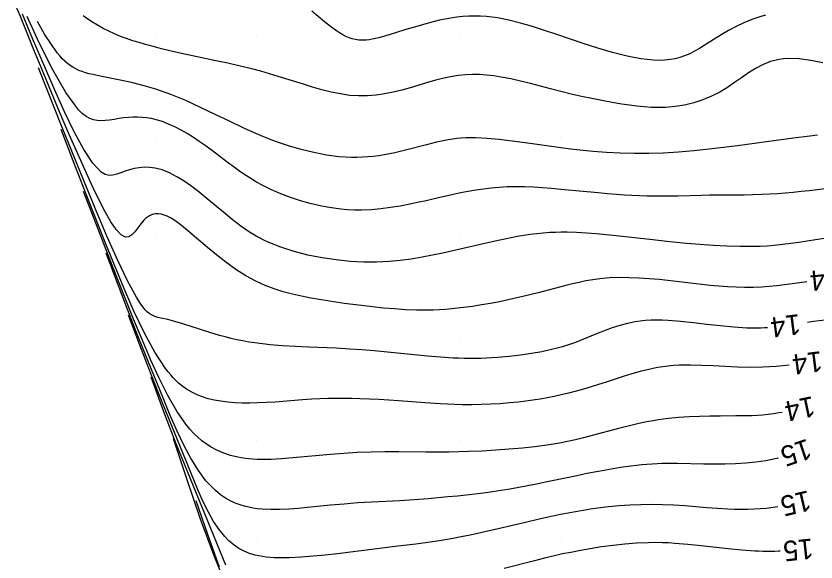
# Model space of a CAD drawing. Extents: x 2602990 to 2605851, y 618069 to 619180.
# Drawn here: x 2603136.2 to 2603215.3, y 618118 to 618172 of the extents above; entities that cross this region are included whole.
import ezdxf

# ---------------------------------------------------------------- set-up
doc = ezdxf.new("R2010")
doc.units = 0
for name, color, linetype in [('DTM Contours Major', 7, 'Continuous'), ('DTM Contours Major Text', 7, 'Continuous'), ('DTM Contours Minor', 7, 'Continuous'), ('DTM Contours Minor Text', 7, 'Continuous'), ('Exist DTM QL2 LIDAR Elevation Point', 7, 'Continuous')]:
    doc.layers.add(name, color=color, linetype=linetype)

msp = doc.modelspace()

# ---------------------------------------------------------------- linework, layer by layer
at = {"layer": 'DTM Contours Major'}
for points in [[(2603210.47, 618141.157), (2603210.172, 618141.14), (2603209.828, 618141.126), (2603209.483, 618141.118), (2603209.137, 618141.115), (2603208.788, 618141.118), (2603208.436, 618141.127), (2603207.132, 618141.204), (2603205.803, 618141.331), (2603204.471, 618141.486), (2603203.155, 618141.646), (2603201.878, 618141.786), (2603200.658, 618141.883), (2603200.075, 618141.909), (2603199.509, 618141.916), (2603198.959, 618141.905), (2603198.424, 618141.873), (2603197.901, 618141.821), (2603197.389, 618141.746), (2603196.617, 618141.586), (2603195.865, 618141.381), (2603195.133, 618141.142), (2603194.421, 618140.88), (2603193.728, 618140.605), (2603192.276, 618140.012), (2603191.89, 618139.861), (2603191.503, 618139.714), (2603191.111, 618139.572), (2603190.712, 618139.437), (2603190.206, 618139.279), (2603189.68, 618139.13), (2603189.129, 618138.99), (2603188.16, 618138.78), (2603187.127, 618138.594), (2603186.045, 618138.437), (2603184.929, 618138.308), (2603183.797, 618138.211), (2603182.663, 618138.147), (2603182.12, 618138.128), (2603181.578, 618138.118), (2603181.036, 618138.115), (2603180.491, 618138.121), (2603179.941, 618138.136), (2603179.384, 618138.158), (2603178.131, 618138.236), (2603176.846, 618138.343), (2603175.539, 618138.471), (2603172.902, 618138.745), (2603171.593, 618138.87), (2603170.38, 618138.97), (2603169.163, 618139.052), (2603167.819, 618139.125), (2603165.119, 618139.245), (2603163.801, 618139.308), (2603162.527, 618139.383), (2603161.317, 618139.478), (2603160.544, 618139.558), (2603159.799, 618139.653), (2603159.197, 618139.746), (2603158.606, 618139.852), (2603158.024, 618139.971), (2603157.448, 618140.103), (2603156.875, 618140.247), (2603156.302, 618140.404), (2603155.354, 618140.686), (2603154.419, 618140.984), (2603152.66, 618141.554), (2603151.876, 618141.79), (2603151.181, 618141.969), (2603150.493, 618142.108), (2603150.188, 618142.177), (2603149.902, 618142.265), (2603149.628, 618142.388), (2603149.359, 618142.561), (2603149.159, 618142.73), (2603148.956, 618142.937), (2603148.748, 618143.185), (2603148.534, 618143.474), (2603148.312, 618143.807), (2603148.079, 618144.186), (2603147.212, 618145.792), (2603146.241, 618147.819), (2603145.204, 618150.147), (2603144.137, 618152.655), (2603143.077, 618155.223), (2603142.059, 618157.732), (2603140.756, 618160.976), (2603138.407, 618166.881)], [(2603216.138, 618141.923), (2603215.029, 618141.76), (2603214.435, 618141.666)]]:
    msp.add_lwpolyline(points, dxfattribs=at)
at = {"layer": 'DTM Contours Minor'}
for points in [[(2603214.371, 618145.696), (2603212.917, 618145.499), (2603212.16, 618145.402), (2603211.404, 618145.314), (2603210.647, 618145.242), (2603209.889, 618145.188), (2603209.053, 618145.155), (2603208.213, 618145.149), (2603207.368, 618145.166), (2603206.519, 618145.206), (2603205.666, 618145.264), (2603204.809, 618145.34), (2603203.981, 618145.427), (2603202.313, 618145.625), (2603200.627, 618145.826), (2603199.776, 618145.916), (2603198.78, 618146.005), (2603197.784, 618146.071), (2603196.792, 618146.11), (2603195.812, 618146.114), (2603194.849, 618146.079), (2603193.911, 618145.999), (2603193.211, 618145.906), (2603192.527, 618145.787), (2603191.854, 618145.649), (2603191.189, 618145.494), (2603190.531, 618145.33), (2603187.814, 618144.62), (2603187.119, 618144.443), (2603186.417, 618144.271), (2603185.707, 618144.104), (2603184.842, 618143.913), (2603183.967, 618143.733), (2603183.084, 618143.565), (2603182.198, 618143.412), (2603181.31, 618143.275), (2603180.425, 618143.155), (2603179.831, 618143.085), (2603179.237, 618143.025), (2603178.641, 618142.975), (2603178.04, 618142.937), (2603177.432, 618142.91), (2603176.813, 618142.897), (2603175.768, 618142.904), (2603174.697, 618142.945), (2603173.609, 618143.015), (2603172.512, 618143.108), (2603171.414, 618143.22), (2603170.324, 618143.345), (2603169.477, 618143.452), (2603168.638, 618143.565), (2603167.806, 618143.685), (2603166.977, 618143.814), (2603166.152, 618143.952), (2603165.327, 618144.1), (2603164.418, 618144.278), (2603163.511, 618144.479), (2603162.607, 618144.714), (2603161.71, 618144.992), (2603160.822, 618145.323), (2603159.946, 618145.718), (2603158.91, 618146.285), (2603157.903, 618146.932), (2603156.929, 618147.634), (2603155.996, 618148.364), (2603155.111, 618149.097), (2603153.37, 618150.586), (2603152.945, 618150.94), (2603152.537, 618151.266), (2603152.147, 618151.559), (2603151.773, 618151.817), (2603151.444, 618152.018), (2603151.127, 618152.183), (2603150.822, 618152.309), (2603150.529, 618152.395), (2603150.248, 618152.438), (2603149.978, 618152.435), (2603149.767, 618152.397), (2603149.563, 618152.33), (2603149.367, 618152.233), (2603149.178, 618152.111), (2603148.997, 618151.964), (2603148.824, 618151.795), (2603148.513, 618151.425), (2603148.22, 618151.027), (2603147.935, 618150.651), (2603147.647, 618150.343), (2603147.345, 618150.152), (2603147.022, 618150.124), (2603146.583, 618150.361), (2603146.099, 618150.88), (2603145.573, 618151.645), (2603145.009, 618152.622), (2603144.412, 618153.775), (2603143.784, 618155.069), (2603142.978, 618156.808), (2603142.147, 618158.66), (2603141.31, 618160.58), (2603140.482, 618162.518), (2603139.679, 618164.429), (2603138.918, 618166.264), (2603137.943, 618168.642), (2603136.61, 618171.936), (2603136.181, 618173.001)], [(2603210.276, 618172.072), (2603209.73, 618171.924), (2603208.928, 618171.652), (2603208.14, 618171.329), (2603207.371, 618170.964), (2603206.623, 618170.567), (2603205.9, 618170.149), (2603205.204, 618169.719), (2603204.228, 618169.092), (2603203.75, 618168.795), (2603203.271, 618168.518), (2603202.784, 618168.268), (2603202.283, 618168.053), (2603201.821, 618167.895), (2603201.342, 618167.771), (2603200.842, 618167.681), (2603200.318, 618167.625), (2603199.769, 618167.605), (2603199.191, 618167.621), (2603197.937, 618167.762), (2603196.585, 618168.025), (2603195.166, 618168.386), (2603193.707, 618168.816), (2603192.238, 618169.289), (2603189.642, 618170.169), (2603188.424, 618170.577), (2603187.231, 618170.958), (2603186.061, 618171.297), (2603184.916, 618171.583), (2603183.793, 618171.802), (2603182.694, 618171.942), (2603182.105, 618171.981), (2603181.521, 618171.993), (2603180.939, 618171.979), (2603180.356, 618171.941), (2603179.77, 618171.878), (2603179.18, 618171.792), (2603178.049, 618171.57), (2603176.912, 618171.29), (2603175.792, 618170.974), (2603174.709, 618170.646), (2603173.685, 618170.327), (2603172.741, 618170.042), (2603172.381, 618169.939), (2603172.037, 618169.848), (2603171.708, 618169.769), (2603171.392, 618169.703), (2603171.089, 618169.653), (2603170.796, 618169.619), (2603170.61, 618169.607), (2603170.428, 618169.602), (2603170.249, 618169.606), (2603170.072, 618169.618), (2603169.898, 618169.639), (2603169.724, 618169.668), (2603169.415, 618169.744), (2603169.107, 618169.848), (2603168.798, 618169.98), (2603168.487, 618170.14), (2603168.172, 618170.325), (2603167.851, 618170.536), (2603167.28, 618170.957), (2603166.687, 618171.435), (2603165.437, 618172.49)], [(2603216.75, 618150.1), (2603215.203, 618149.854), (2603213.584, 618149.597), (2603212.773, 618149.481), (2603211.957, 618149.378), (2603211.129, 618149.293), (2603210.45, 618149.24), (2603209.755, 618149.202), (2603209.039, 618149.18), (2603207.773, 618149.179), (2603206.457, 618149.217), (2603205.117, 618149.288), (2603203.778, 618149.383), (2603202.469, 618149.495), (2603200.807, 618149.658), (2603198.825, 618149.874), (2603195.524, 618150.243), (2603194.536, 618150.345), (2603193.547, 618150.436), (2603192.565, 618150.512), (2603191.602, 618150.567), (2603190.669, 618150.597), (2603190.085, 618150.601), (2603189.514, 618150.591), (2603188.953, 618150.568), (2603188.305, 618150.522), (2603187.664, 618150.458), (2603187.027, 618150.378), (2603186.395, 618150.284), (2603185.764, 618150.177), (2603185.135, 618150.06), (2603184.491, 618149.932), (2603183.846, 618149.796), (2603182.544, 618149.505), (2603179.358, 618148.763), (2603178.385, 618148.545), (2603177.37, 618148.332), (2603176.324, 618148.133), (2603175.254, 618147.956), (2603174.169, 618147.811), (2603173.076, 618147.707), (2603172.445, 618147.669), (2603171.811, 618147.647), (2603171.173, 618147.642), (2603170.527, 618147.654), (2603169.872, 618147.682), (2603169.205, 618147.726), (2603167.841, 618147.865), (2603166.446, 618148.071), (2603165.047, 618148.347), (2603163.673, 618148.695), (2603162.35, 618149.119), (2603161.105, 618149.619), (2603160.669, 618149.824), (2603160.245, 618150.042), (2603159.914, 618150.225), (2603159.429, 618150.515), (2603159.27, 618150.616), (2603158.396, 618151.217), (2603157.547, 618151.865), (2603156.718, 618152.543), (2603155.096, 618153.914), (2603154.291, 618154.57), (2603153.552, 618155.134), (2603152.813, 618155.648), (2603152.08, 618156.099), (2603151.356, 618156.476), (2603150.645, 618156.764), (2603149.951, 618156.952), (2603149.4, 618157.025), (2603148.866, 618157.033), (2603148.353, 618156.987), (2603147.862, 618156.898), (2603147.398, 618156.777), (2603146.962, 618156.634), (2603146.543, 618156.478), (2603146.148, 618156.34), (2603145.768, 618156.248), (2603145.391, 618156.234), (2603145.01, 618156.324), (2603144.613, 618156.55), (2603143.781, 618157.424), (2603142.88, 618158.793), (2603141.935, 618160.535), (2603140.971, 618162.531), (2603140.013, 618164.661), (2603139.086, 618166.802), (2603137.827, 618169.76), (2603136.81, 618172.183)], [(2603217.226, 618155.04), (2603214.578, 618154.71), (2603213.793, 618154.621), (2603213.011, 618154.541), (2603212.23, 618154.471), (2603211.45, 618154.411), (2603210.668, 618154.363), (2603209.886, 618154.327), (2603209.027, 618154.302), (2603208.167, 618154.289), (2603205.591, 618154.275), (2603204.74, 618154.265), (2603203.951, 618154.248), (2603201.607, 618154.182), (2603200.83, 618154.166), (2603200.054, 618154.158), (2603199.314, 618154.162), (2603198.572, 618154.176), (2603197.827, 618154.201), (2603197.077, 618154.236), (2603196.321, 618154.281), (2603195.556, 618154.334), (2603194.653, 618154.407), (2603193.74, 618154.489), (2603190.032, 618154.848), (2603189.132, 618154.928), (2603188.236, 618154.998), (2603187.346, 618155.053), (2603186.463, 618155.089), (2603185.589, 618155.101), (2603184.726, 618155.085), (2603183.938, 618155.042), (2603183.159, 618154.973), (2603182.388, 618154.881), (2603181.624, 618154.768), (2603180.866, 618154.637), (2603180.112, 618154.49), (2603179.44, 618154.348), (2603178.095, 618154.041), (2603176.732, 618153.724), (2603176.038, 618153.568), (2603175.107, 618153.371), (2603174.16, 618153.192), (2603173.204, 618153.037), (2603172.244, 618152.914), (2603171.284, 618152.831), (2603170.331, 618152.795), (2603169.646, 618152.802), (2603168.965, 618152.837), (2603168.287, 618152.898), (2603167.609, 618152.984), (2603166.929, 618153.094), (2603166.247, 618153.228), (2603165.269, 618153.455), (2603164.291, 618153.725), (2603163.322, 618154.037), (2603162.372, 618154.391), (2603161.451, 618154.786), (2603160.568, 618155.22), (2603159.965, 618155.554), (2603159.384, 618155.906), (2603158.82, 618156.272), (2603158.271, 618156.65), (2603157.733, 618157.037), (2603157.202, 618157.431), (2603155.464, 618158.748), (2603154.885, 618159.175), (2603154.304, 618159.588), (2603153.718, 618159.982), (2603153.111, 618160.363), (2603152.499, 618160.714), (2603151.884, 618161.032), (2603151.269, 618161.31), (2603150.656, 618161.545), (2603150.047, 618161.732), (2603149.574, 618161.842), (2603149.105, 618161.922), (2603148.642, 618161.972), (2603148.184, 618161.994), (2603147.734, 618161.991), (2603147.29, 618161.965), (2603146.808, 618161.91), (2603146.335, 618161.841), (2603145.874, 618161.767), (2603145.424, 618161.701), (2603144.987, 618161.655), (2603144.562, 618161.639), (2603144.203, 618161.661), (2603143.848, 618161.727), (2603143.493, 618161.853), (2603143.132, 618162.049), (2603142.759, 618162.33), (2603142.37, 618162.708), (2603141.111, 618164.417), (2603139.733, 618166.833), (2603138.308, 618169.704), (2603137.279, 618171.962)], [(2603215.943, 618167.362), (2603214.745, 618167.606), (2603213.601, 618167.751), (2603212.526, 618167.777), (2603212.068, 618167.744), (2603211.627, 618167.684), (2603211.199, 618167.596), (2603210.784, 618167.48), (2603210.38, 618167.337), (2603209.984, 618167.168), (2603209.285, 618166.798), (2603208.598, 618166.364), (2603207.913, 618165.892), (2603207.221, 618165.404), (2603206.51, 618164.924), (2603205.771, 618164.476), (2603204.943, 618164.056), (2603204.079, 618163.701), (2603203.186, 618163.411), (2603202.271, 618163.189), (2603201.343, 618163.034), (2603200.409, 618162.949), (2603199.699, 618162.93), (2603198.988, 618162.947), (2603198.273, 618162.996), (2603197.553, 618163.07), (2603196.825, 618163.165), (2603196.087, 618163.276), (2603195.106, 618163.44), (2603194.109, 618163.623), (2603193.1, 618163.823), (2603192.083, 618164.04), (2603191.063, 618164.273), (2603190.043, 618164.522), (2603189.031, 618164.783), (2603187.033, 618165.308), (2603186.054, 618165.552), (2603185.092, 618165.771), (2603184.149, 618165.955), (2603183.421, 618166.069), (2603182.705, 618166.152), (2603181.999, 618166.201), (2603181.3, 618166.214), (2603180.606, 618166.187), (2603179.916, 618166.119), (2603179.128, 618165.99), (2603178.339, 618165.814), (2603177.548, 618165.604), (2603176.754, 618165.373), (2603175.15, 618164.893), (2603174.315, 618164.664), (2603173.474, 618164.459), (2603172.626, 618164.289), (2603171.773, 618164.163), (2603170.915, 618164.092), (2603170.054, 618164.083), (2603169.151, 618164.148), (2603168.246, 618164.281), (2603167.337, 618164.47), (2603166.425, 618164.701), (2603165.509, 618164.964), (2603164.588, 618165.245), (2603162.095, 618166.023), (2603161.246, 618166.277), (2603160.384, 618166.523), (2603159.507, 618166.759), (2603158.326, 618167.048), (2603157.132, 618167.317), (2603155.94, 618167.569), (2603153.632, 618168.046), (2603152.549, 618168.279), (2603151.528, 618168.515), (2603150.561, 618168.755), (2603149.631, 618168.999), (2603148.986, 618169.176), (2603148.352, 618169.36), (2603147.729, 618169.553), (2603147.117, 618169.758), (2603146.516, 618169.98), (2603145.927, 618170.222), (2603145.349, 618170.486), (2603144.783, 618170.774), (2603144.227, 618171.084), (2603143.683, 618171.417), (2603143.148, 618171.772), (2603142.836, 618171.998)], [(2603215.405, 618160.195), (2603214.647, 618160.112), (2603213.047, 618159.918), (2603211.331, 618159.694), (2603207.511, 618159.169), (2603206.112, 618158.984), (2603204.663, 618158.807), (2603203.177, 618158.649), (2603201.671, 618158.521), (2603200.161, 618158.432), (2603198.73, 618158.392), (2603197.316, 618158.393), (2603195.923, 618158.431), (2603194.557, 618158.502), (2603193.225, 618158.602), (2603191.932, 618158.726), (2603190.984, 618158.833), (2603190.051, 618158.95), (2603189.119, 618159.077), (2603186.507, 618159.453), (2603185.216, 618159.63), (2603183.956, 618159.779), (2603182.746, 618159.888), (2603181.602, 618159.941), (2603181.126, 618159.944), (2603180.661, 618159.932), (2603180.205, 618159.905), (2603179.775, 618159.865), (2603179.377, 618159.815), (2603178.904, 618159.74), (2603178.744, 618159.712), (2603177.766, 618159.508), (2603176.757, 618159.263), (2603174.679, 618158.728), (2603173.625, 618158.477), (2603172.572, 618158.265), (2603172.039, 618158.177), (2603171.506, 618158.106), (2603170.972, 618158.052), (2603170.433, 618158.016), (2603169.889, 618157.999), (2603169.338, 618158.002), (2603168.12, 618158.079), (2603166.874, 618158.243), (2603165.616, 618158.484), (2603164.362, 618158.79), (2603163.128, 618159.15), (2603161.931, 618159.555), (2603161.251, 618159.808), (2603160.579, 618160.076), (2603159.907, 618160.36), (2603159.066, 618160.736), (2603158.635, 618160.935), (2603157.293, 618161.577), (2603155.886, 618162.261), (2603154.434, 618162.954), (2603152.956, 618163.624), (2603151.475, 618164.238), (2603150.009, 618164.762), (2603148.851, 618165.104), (2603147.726, 618165.383), (2603146.646, 618165.616), (2603144.659, 618166.007), (2603143.774, 618166.199), (2603143.412, 618166.288), (2603143.066, 618166.385), (2603142.732, 618166.494), (2603142.409, 618166.619), (2603142.096, 618166.764), (2603141.79, 618166.933), (2603141.53, 618167.102), (2603141.272, 618167.296), (2603141.015, 618167.515), (2603140.758, 618167.764), (2603140.499, 618168.045), (2603140.236, 618168.36), (2603138.997, 618170.2), (2603138.318, 618171.455)], [(2603212.628, 618137.453), (2603212.613, 618137.451), (2603211.314, 618137.325), (2603210.011, 618137.248), (2603208.758, 618137.232), (2603207.518, 618137.26), (2603206.3, 618137.315), (2603205.112, 618137.379), (2603203.962, 618137.433), (2603202.859, 618137.46), (2603202.291, 618137.457), (2603201.736, 618137.44), (2603201.192, 618137.408), (2603200.656, 618137.361), (2603200.127, 618137.296), (2603199.6, 618137.214), (2603198.747, 618137.042), (2603197.896, 618136.83), (2603197.047, 618136.588), (2603196.2, 618136.325), (2603194.513, 618135.775), (2603193.771, 618135.537), (2603193.03, 618135.308), (2603192.289, 618135.088), (2603191.548, 618134.88), (2603190.806, 618134.686), (2603190.063, 618134.507), (2603189.376, 618134.358), (2603188.686, 618134.223), (2603187.992, 618134.101), (2603187.291, 618133.992), (2603186.583, 618133.896), (2603185.865, 618133.81), (2603184.954, 618133.719), (2603184.03, 618133.645), (2603183.098, 618133.59), (2603182.163, 618133.553), (2603181.228, 618133.537), (2603180.297, 618133.542), (2603179.562, 618133.562), (2603178.831, 618133.592), (2603178.1, 618133.633), (2603176.635, 618133.733), (2603174.004, 618133.93), (2603173.048, 618133.995), (2603172.09, 618134.054), (2603171.133, 618134.103), (2603170.179, 618134.14), (2603169.38, 618134.159), (2603168.584, 618134.167), (2603167.791, 618134.164), (2603166.999, 618134.149), (2603166.207, 618134.122), (2603165.414, 618134.082), (2603164.509, 618134.022), (2603161.81, 618133.811), (2603160.926, 618133.754), (2603160.056, 618133.714), (2603159.299, 618133.699), (2603158.556, 618133.705), (2603157.829, 618133.737), (2603157.12, 618133.795), (2603156.429, 618133.883), (2603155.759, 618134.004), (2603155.184, 618134.14), (2603154.625, 618134.309), (2603154.081, 618134.519), (2603153.551, 618134.776), (2603153.034, 618135.086), (2603152.53, 618135.455), (2603152.262, 618135.682), (2603151.998, 618135.929), (2603151.735, 618136.197), (2603151.474, 618136.488), (2603151.213, 618136.802), (2603150.953, 618137.14), (2603149.912, 618138.727), (2603148.872, 618140.636), (2603147.841, 618142.787), (2603146.827, 618145.097), (2603145.838, 618147.502), (2603144.884, 618149.868), (2603143.403, 618153.626), (2603141.999, 618157.232), (2603140.633, 618160.76)], [(2603211.907, 618132.776), (2603211.617, 618132.726), (2603211.071, 618132.644), (2603210.53, 618132.576), (2603209.991, 618132.523), (2603209.471, 618132.485), (2603208.947, 618132.459), (2603208.418, 618132.443), (2603207.334, 618132.43), (2603205.793, 618132.425), (2603204.782, 618132.416), (2603203.751, 618132.393), (2603202.715, 618132.351), (2603201.686, 618132.284), (2603200.676, 618132.184), (2603200.177, 618132.12), (2603199.684, 618132.046), (2603199.196, 618131.964), (2603198.711, 618131.873), (2603198.229, 618131.775), (2603197.747, 618131.67), (2603196.818, 618131.451), (2603195.889, 618131.216), (2603193.155, 618130.49), (2603192.278, 618130.266), (2603191.496, 618130.079), (2603190.718, 618129.909), (2603189.925, 618129.754), (2603189.302, 618129.646), (2603188.652, 618129.545), (2603187.482, 618129.389), (2603186.238, 618129.252), (2603184.94, 618129.134), (2603183.607, 618129.036), (2603182.26, 618128.959), (2603180.919, 618128.902), (2603179.945, 618128.874), (2603178.972, 618128.857), (2603177.99, 618128.85), (2603176.693, 618128.853), (2603174.017, 618128.872), (2603172.652, 618128.87), (2603171.279, 618128.849), (2603169.907, 618128.8), (2603168.576, 618128.719), (2603167.263, 618128.615), (2603163.541, 618128.275), (2603162.409, 618128.189), (2603161.906, 618128.16), (2603161.418, 618128.139), (2603160.942, 618128.128), (2603160.477, 618128.127), (2603160.02, 618128.139), (2603159.571, 618128.164), (2603158.83, 618128.239), (2603158.106, 618128.36), (2603157.4, 618128.532), (2603156.714, 618128.758), (2603156.048, 618129.042), (2603155.404, 618129.39), (2603154.979, 618129.665), (2603154.563, 618129.974), (2603154.156, 618130.32), (2603153.756, 618130.706), (2603153.362, 618131.135), (2603152.973, 618131.61), (2603152.073, 618132.912), (2603151.193, 618134.442), (2603150.328, 618136.159), (2603149.478, 618138.021), (2603148.638, 618139.987), (2603147.806, 618142.014), (2603146.973, 618144.087), (2603146.144, 618146.177), (2603145.32, 618148.281), (2603143.677, 618152.516), (2603142.858, 618154.64)], [(2603211.576, 618128.263), (2603211.234, 618128.18), (2603210.772, 618128.08), (2603210.301, 618127.992), (2603209.82, 618127.915), (2603209.328, 618127.849), (2603208.332, 618127.751), (2603207.304, 618127.69), (2603206.26, 618127.659), (2603205.214, 618127.651), (2603204.185, 618127.66), (2603201.587, 618127.717), (2603201.072, 618127.723), (2603200.562, 618127.724), (2603200.054, 618127.717), (2603199.557, 618127.701), (2603199.057, 618127.676), (2603198.551, 618127.642), (2603198.037, 618127.597), (2603197.511, 618127.542), (2603196.972, 618127.476), (2603195.94, 618127.328), (2603194.863, 618127.148), (2603193.754, 618126.945), (2603192.624, 618126.723), (2603191.485, 618126.489), (2603188.539, 618125.869), (2603187.646, 618125.685), (2603186.759, 618125.509), (2603185.878, 618125.343), (2603185.001, 618125.189), (2603184.136, 618125.05), (2603183.273, 618124.923), (2603182.411, 618124.808), (2603181.549, 618124.702), (2603180.686, 618124.604), (2603179.821, 618124.512), (2603178.86, 618124.416), (2603177.9, 618124.327), (2603176.943, 618124.246), (2603175.995, 618124.172), (2603175.059, 618124.106), (2603174.139, 618124.05), (2603171.335, 618123.909), (2603170.649, 618123.871), (2603169.965, 618123.826), (2603169.299, 618123.776), (2603168.631, 618123.719), (2603167.284, 618123.59), (2603164.996, 618123.36), (2603164.071, 618123.277), (2603163.152, 618123.212), (2603162.246, 618123.173), (2603161.364, 618123.169), (2603160.516, 618123.209), (2603160.061, 618123.253), (2603159.617, 618123.316), (2603159.186, 618123.397), (2603158.765, 618123.5), (2603158.354, 618123.624), (2603157.951, 618123.772), (2603157.42, 618124.013), (2603156.902, 618124.302), (2603156.397, 618124.645), (2603155.906, 618125.044), (2603155.427, 618125.505), (2603154.96, 618126.029), (2603154.224, 618127.024), (2603153.511, 618128.183), (2603152.814, 618129.49), (2603152.124, 618130.926), (2603151.434, 618132.477), (2603150.749, 618134.134), (2603148.909, 618138.644), (2603147.966, 618141.031), (2603147.012, 618143.491), (2603145.084, 618148.52)], [(2603211.499, 618123.434), (2603211.261, 618123.396), (2603210.383, 618123.289), (2603209.754, 618123.236), (2603209.125, 618123.2), (2603208.491, 618123.182), (2603207.852, 618123.18), (2603207.204, 618123.192), (2603206.544, 618123.217), (2603205.518, 618123.278), (2603204.465, 618123.357), (2603202.302, 618123.527), (2603201.204, 618123.599), (2603200.1, 618123.647), (2603199.021, 618123.664), (2603197.945, 618123.65), (2603196.874, 618123.607), (2603195.809, 618123.535), (2603194.752, 618123.435), (2603193.706, 618123.31), (2603192.97, 618123.205), (2603192.237, 618123.088), (2603191.503, 618122.959), (2603190.763, 618122.819), (2603190.013, 618122.668), (2603189.251, 618122.507), (2603187.913, 618122.209), (2603186.549, 618121.893), (2603183.841, 618121.255), (2603182.545, 618120.957), (2603181.087, 618120.639), (2603180.19, 618120.459), (2603179.385, 618120.31), (2603178.811, 618120.212), (2603178.245, 618120.12), (2603177.121, 618119.953), (2603175.7, 618119.76), (2603173.934, 618119.537), (2603167.969, 618118.806), (2603166.76, 618118.67), (2603165.549, 618118.551), (2603164.357, 618118.459), (2603163.208, 618118.405), (2603162.124, 618118.398), (2603161.712, 618118.412), (2603161.314, 618118.436), (2603160.928, 618118.471), (2603160.554, 618118.52), (2603160.192, 618118.584), (2603159.839, 618118.664), (2603159.277, 618118.834), (2603158.739, 618119.054), (2603158.226, 618119.329), (2603157.734, 618119.661), (2603157.263, 618120.054), (2603156.812, 618120.511), (2603156.255, 618121.201), (2603155.72, 618122.002), (2603155.197, 618122.912), (2603154.678, 618123.928), (2603154.185, 618125.048), (2603150.618, 618133.791), (2603149.528, 618136.526), (2603148.424, 618139.439), (2603147.309, 618142.399)], [(2603156.929, 618117.658), (2603152.028, 618129.669), (2603150.784, 618132.832), (2603149.535, 618136.279)], [(2603157.062, 618115.413), (2603155.756, 618118.605), (2603154.433, 618122.221), (2603153.1, 618126.119), (2603151.76, 618130.159)], [(2603156.302, 618117.472), (2603155.145, 618120.705), (2603153.986, 618124.039)], [(2603211.715, 618119.052), (2603211.571, 618119.045), (2603211.186, 618119.035), (2603210.799, 618119.03), (2603210.409, 618119.031), (2603210.015, 618119.037), (2603209.616, 618119.048), (2603209.212, 618119.066), (2603207.926, 618119.153), (2603206.601, 618119.279), (2603203.915, 618119.579), (2603202.595, 618119.718), (2603201.319, 618119.826), (2603200.692, 618119.864), (2603200.077, 618119.888), (2603199.369, 618119.9), (2603198.66, 618119.892), (2603197.525, 618119.842), (2603196.376, 618119.751), (2603195.222, 618119.625), (2603194.072, 618119.47), (2603192.937, 618119.291), (2603191.825, 618119.095), (2603191.016, 618118.94), (2603190.216, 618118.776), (2603189.417, 618118.601), (2603188.426, 618118.365), (2603187.429, 618118.114), (2603184.452, 618117.334)]]:
    msp.add_lwpolyline(points, dxfattribs=at)
at = {"layer": 'Exist DTM QL2 LIDAR Elevation Point'}
for p, q in [((2603140, 618170), (2603140, 618170)), ((2603150, 618170), (2603150, 618170)), ((2603160, 618170), (2603160, 618170)), ((2603170, 618170), (2603170, 618170)), ((2603180, 618170), (2603180, 618170)), ((2603190, 618170), (2603190, 618170)), ((2603200, 618170), (2603200, 618170)), ((2603210, 618170), (2603210, 618170)), ((2603150, 618160), (2603150, 618160)), ((2603160, 618160), (2603160, 618160)), ((2603170, 618160), (2603170, 618160)), ((2603180, 618160), (2603180, 618160)), ((2603190, 618160), (2603190, 618160)), ((2603200, 618160), (2603200, 618160)), ((2603210, 618160), (2603210, 618160)), ((2603150, 618150), (2603150, 618150)), ((2603160, 618150), (2603160, 618150)), ((2603170, 618150), (2603170, 618150)), ((2603180, 618150), (2603180, 618150)), ((2603190, 618150), (2603190, 618150)), ((2603200, 618150), (2603200, 618150)), ((2603210, 618150), (2603210, 618150)), ((2603150, 618140), (2603150, 618140)), ((2603160, 618140), (2603160, 618140)), ((2603170, 618140), (2603170, 618140)), ((2603180, 618140), (2603180, 618140)), ((2603190, 618140), (2603190, 618140)), ((2603200, 618140), (2603200, 618140)), ((2603210, 618140), (2603210, 618140)), ((2603160, 618130), (2603160, 618130)), ((2603170, 618130), (2603170, 618130)), ((2603180, 618130), (2603180, 618130)), ((2603190, 618130), (2603190, 618130)), ((2603200, 618130), (2603200, 618130)), ((2603210, 618130), (2603210, 618130)), ((2603160, 618120), (2603160, 618120)), ((2603170, 618120), (2603170, 618120)), ((2603180, 618120), (2603180, 618120)), ((2603190, 618120), (2603190, 618120)), ((2603200, 618120), (2603200, 618120)), ((2603210, 618120), (2603210, 618120))]:
    msp.add_line(p, q, dxfattribs=at)

# ---------------------------------------------------------------- texts
at = {"layer": 'DTM Contours Major Text'}
msp.add_text('14', height=2, rotation=187.32245, dxfattribs=at).set_placement((2603213.619, 618142.526))
at = {"layer": 'DTM Contours Minor Text'}
for s, rotation, p in [('14', 185.70551, (2603217.55, 618147.062)), ('14', 187.22273, (2603215.776, 618138.855)), ('14', 191.73602, (2603214.937, 618134.409)), ('15', 198.54318, (2603214.402, 618130.207)), ('15', 193.22247, (2603214.497, 618125.088)), ('15', 185.96937, (2603214.898, 618120.324))]:
    msp.add_text(s, height=2, rotation=rotation, dxfattribs=at).set_placement(p)

doc.saveas('drawing.dxf')
